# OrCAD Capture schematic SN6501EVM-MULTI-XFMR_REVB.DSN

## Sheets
1 P01 3p3V No LDO: size A; title: SN6501EVM-Multi-Xfmr; note: 6566239
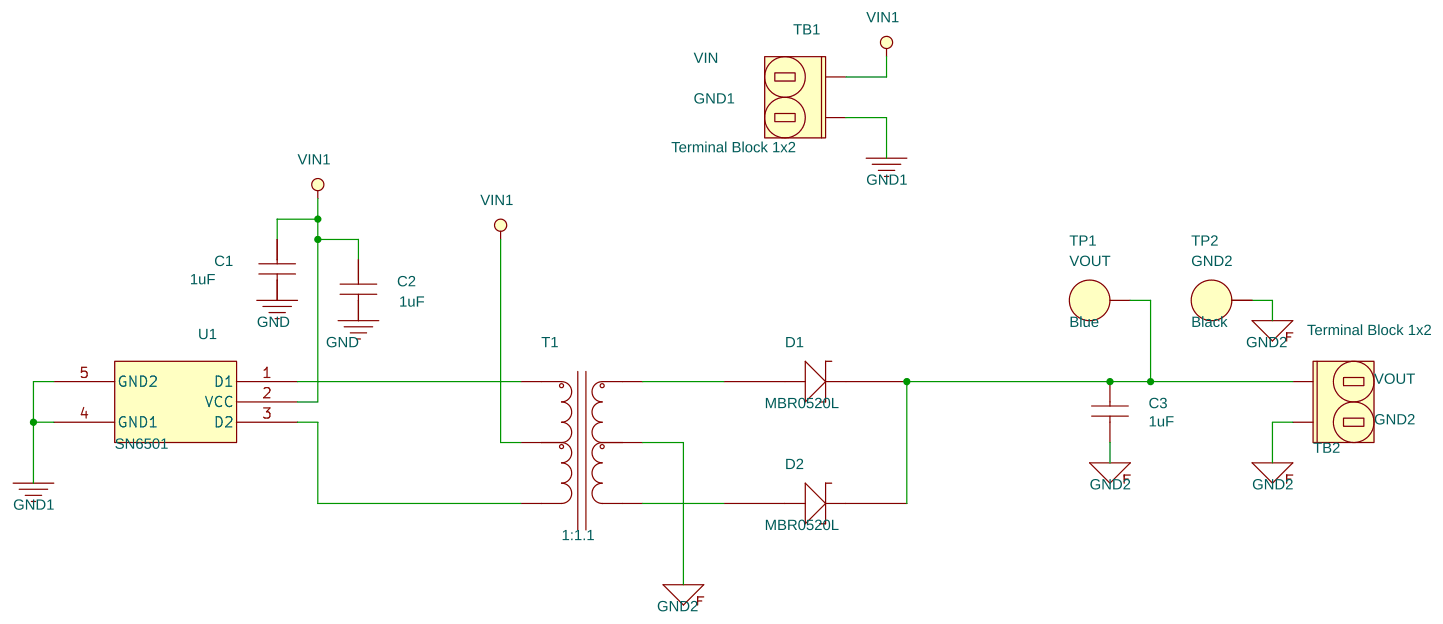
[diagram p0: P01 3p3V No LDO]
2 P02 5V No LDO: size A
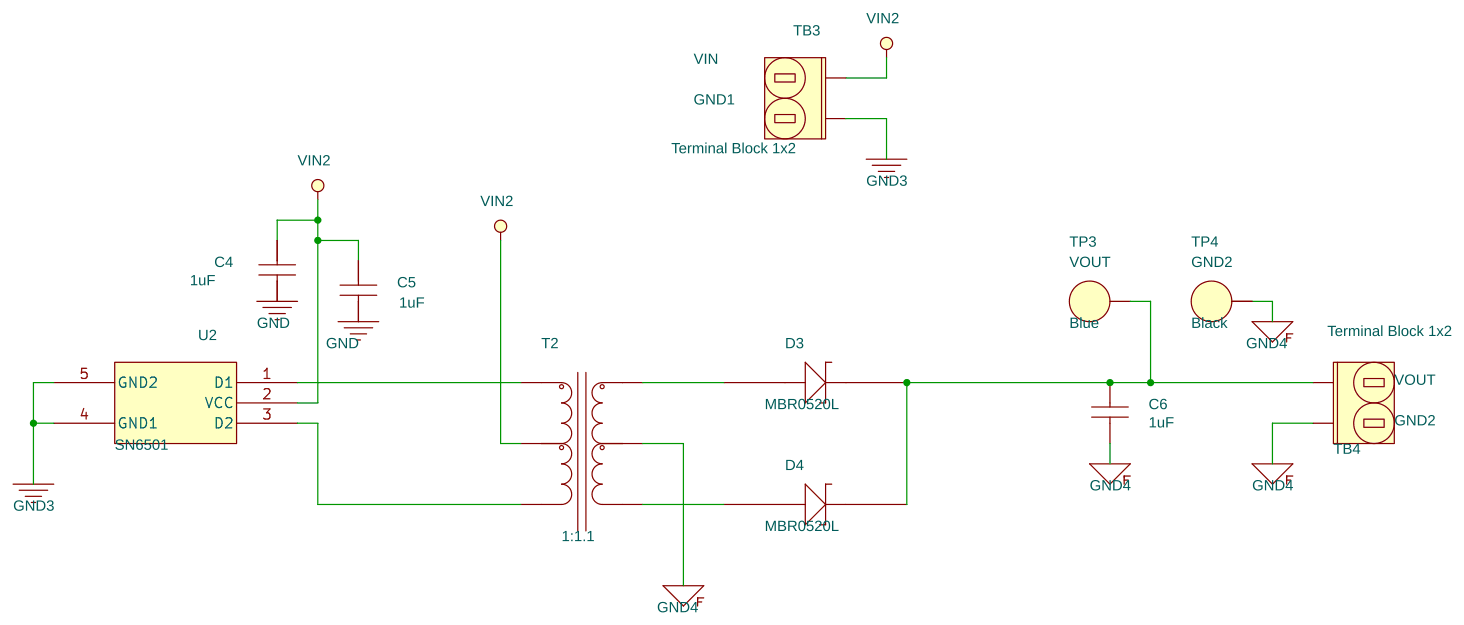
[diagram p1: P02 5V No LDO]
3 P03 3p3V to 5V No LDO: size A
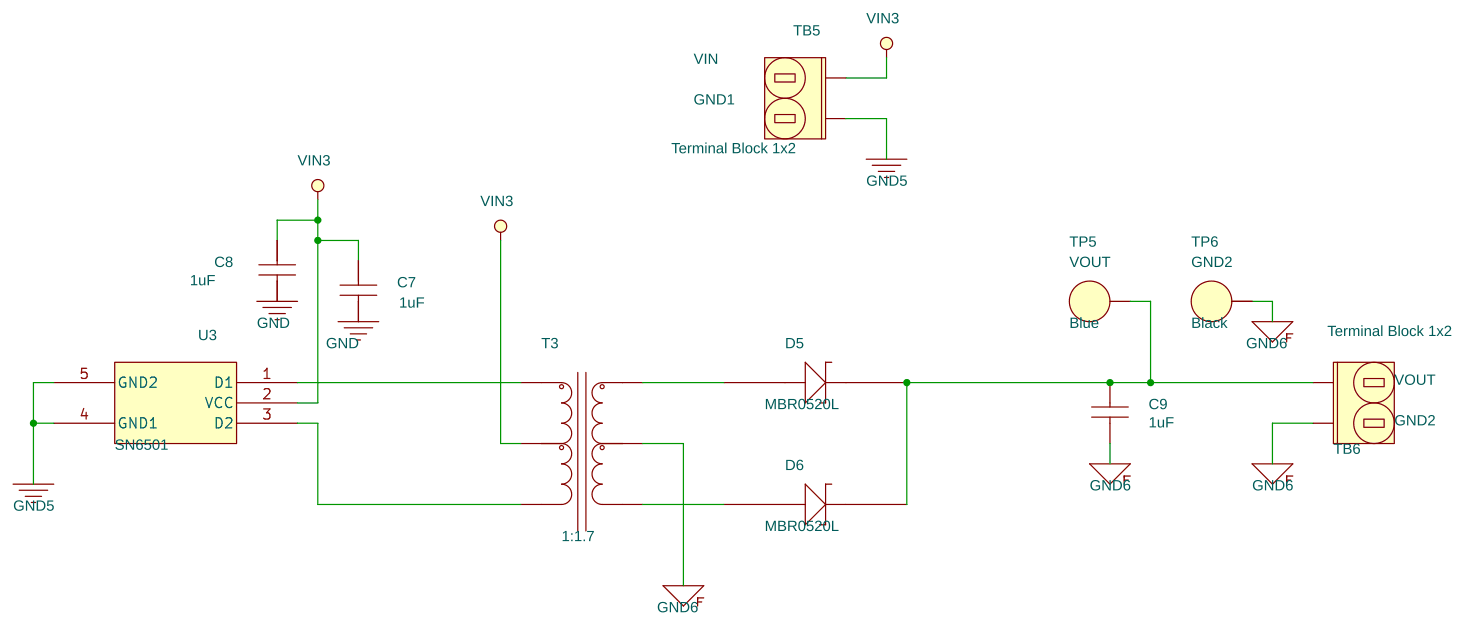
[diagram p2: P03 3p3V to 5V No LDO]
4 P04 3p3V to 5V LDO: size A
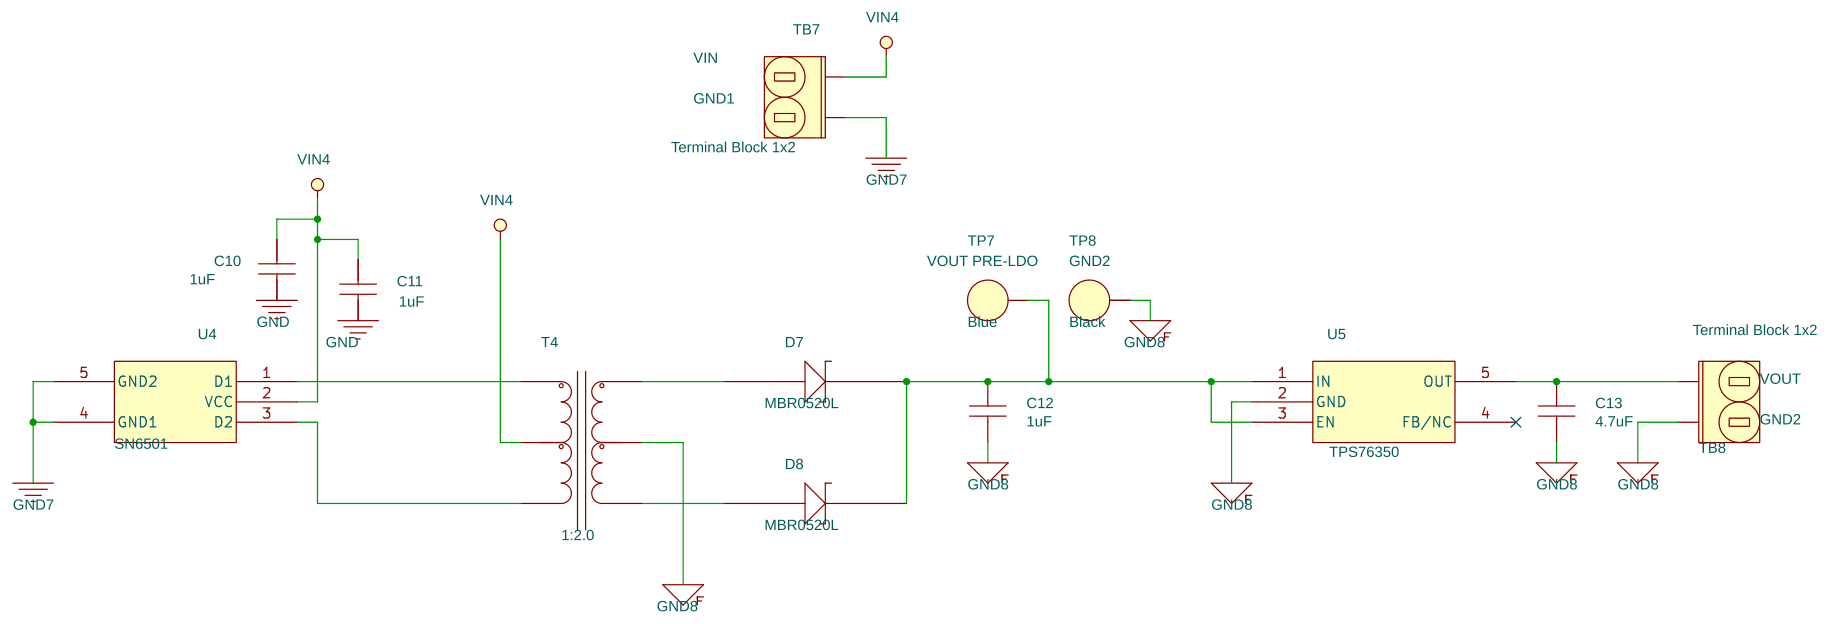
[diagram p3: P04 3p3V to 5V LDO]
5 P05 3p3V or 5V to 3p3V 5V LDO: size A
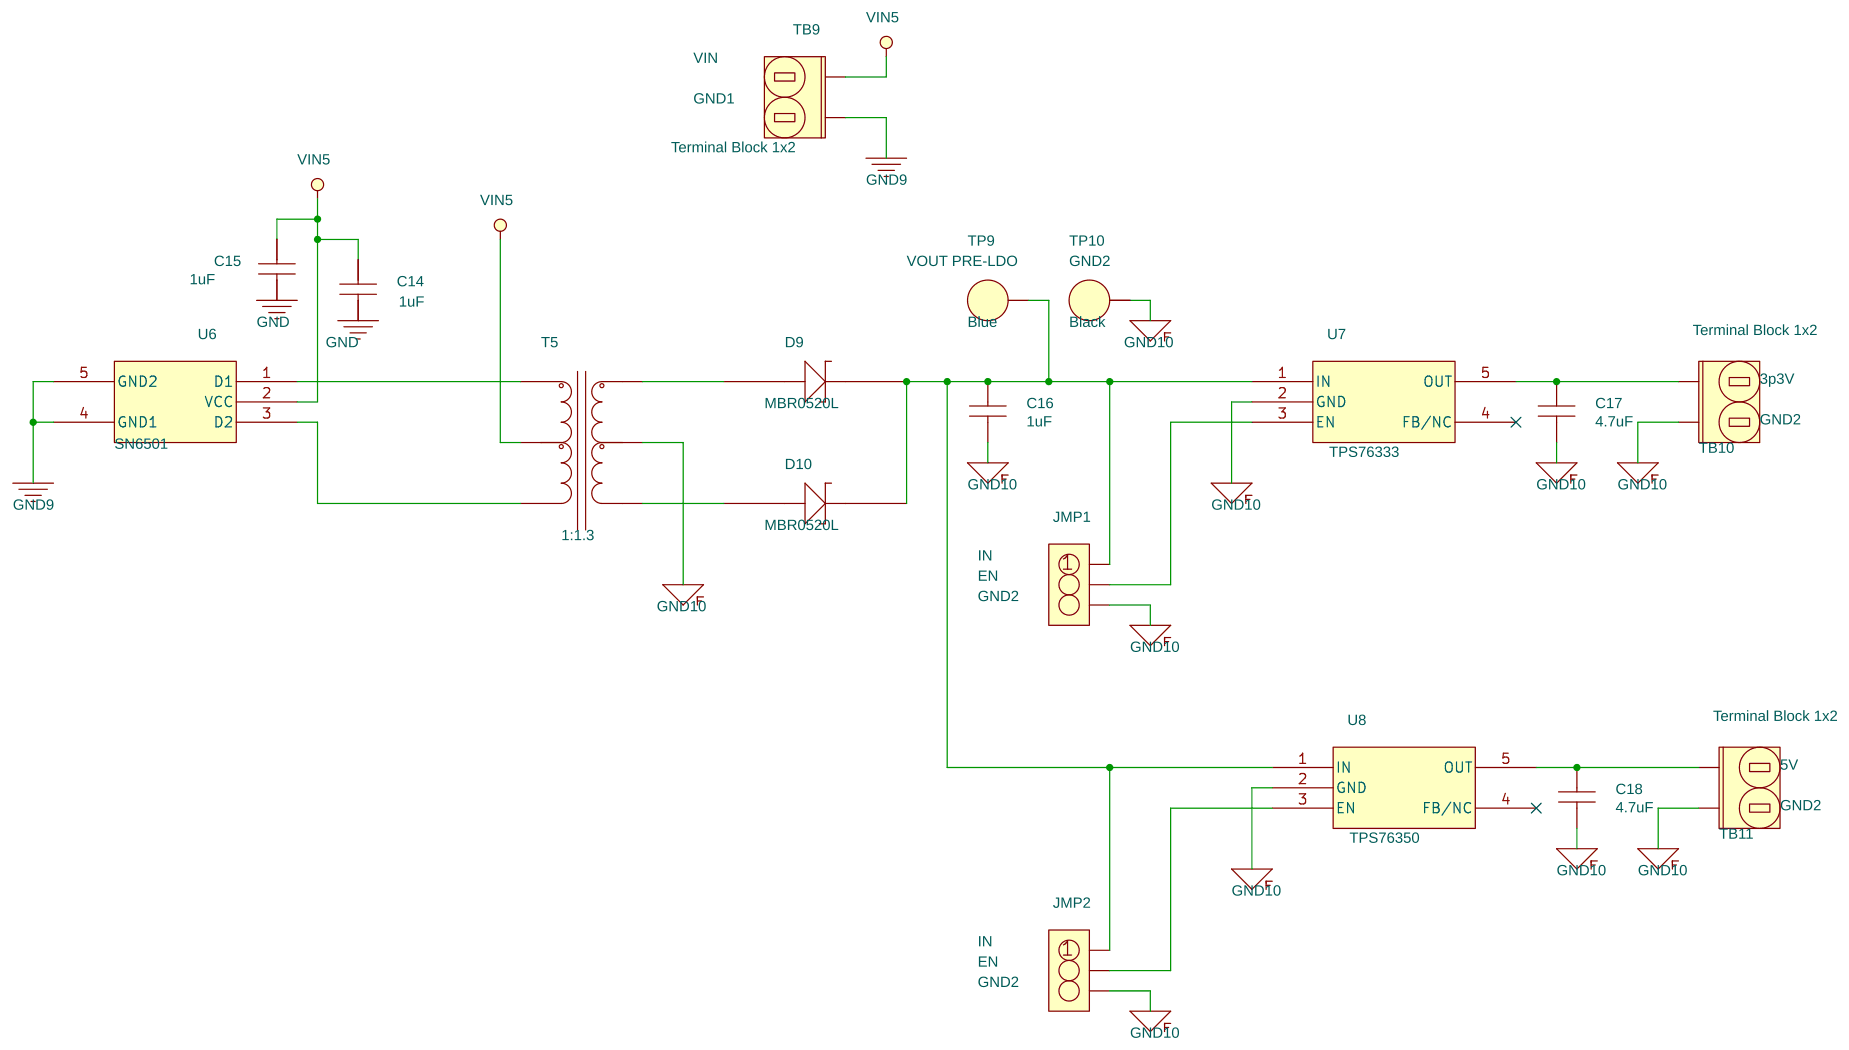
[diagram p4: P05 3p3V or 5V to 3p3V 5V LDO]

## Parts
sheet P01 3p3V No LDO
C1  1uF  [0402]
C2  1uF  [0603]
C3  1uF  [0603]
D1  MBR0520L  [SOD123]
D2  MBR0520L  [SOD123]
T1  1:1.1  [Wurth_76039xxxx]
TB1  Terminal Block 1x2  [TB_THRTSCR_1x2_100]
TB2  Terminal Block 1x2  [TB_THRTSCR_1x2_100]
TP1  Blue  [HDR_THVT_1X1_100]
TP2  Black  [HDR_THVT_1X1_100]
U1  SN6501  [SOT_5DBV]
sheet P02 5V No LDO
C4  1uF  [0402]
C5  1uF  [0603]
C6  1uF  [0603]
D3  MBR0520L  [SOD123]
D4  MBR0520L  [SOD123]
T2  1:1.1  [Wurth_76039xxxx]
TB3  Terminal Block 1x2  [TB_THRTSCR_1x2_100]
TB4  Terminal Block 1x2  [TB_THRTSCR_1x2_100]
TP3  Blue  [HDR_THVT_1X1_100]
TP4  Black  [HDR_THVT_1X1_100]
U2  SN6501  [SOT_5DBV]
sheet P03 3p3V to 5V No LDO
C7  1uF  [0603]
C8  1uF  [0402]
C9  1uF  [0603]
D5  MBR0520L  [SOD123]
D6  MBR0520L  [SOD123]
T3  1:1.7  [Wurth_76039xxxx]
TB5  Terminal Block 1x2  [TB_THRTSCR_1x2_100]
TB6  Terminal Block 1x2  [TB_THRTSCR_1x2_100]
TP5  Blue  [HDR_THVT_1X1_100]
TP6  Black  [HDR_THVT_1X1_100]
U3  SN6501  [SOT_5DBV]
sheet P04 3p3V to 5V LDO
C10  1uF  [0402]
C11  1uF  [0603]
C12  1uF  [0603]
C13  4.7uF  [0603]
D7  MBR0520L  [SOD123]
D8  MBR0520L  [SOD123]
T4  1:2.0  [Wurth_76039xxxx]
TB7  Terminal Block 1x2  [TB_THRTSCR_1x2_100]
TB8  Terminal Block 1x2  [TB_THRTSCR_1x2_100]
TP7  Blue  [HDR_THVT_1X1_100]
TP8  Black  [HDR_THVT_1X1_100]
U4  SN6501  [SOT_5DBV]
U5  TPS76350  [SOT_5DBV]
sheet P05 3p3V or 5V to 3p3V 5V LDO
C14  1uF  [0603]
C15  1uF  [0402]
C16  1uF  [0603]
C17  4.7uF  [0603]
C18  4.7uF  [0603]
D9  MBR0520L  [SOD123]
D10  MBR0520L  [SOD123]
JMP1  Header 1x3  [HDR_THVT_1X3_100]
JMP2  Header 1x3  [HDR_THVT_1X3_100]
T5  1:1.3  [Wurth_76039xxxx]
TB9  Terminal Block 1x2  [TB_THRTSCR_1x2_100]
TB10  Terminal Block 1x2  [TB_THRTSCR_1x2_100]
TB11  Terminal Block 1x2  [TB_THRTSCR_1x2_100]
TP9  Blue  [HDR_THVT_1X1_100]
TP10  Black  [HDR_THVT_1X1_100]
U6  SN6501  [SOT_5DBV]
U7  TPS76333  [SOT_5DBV]
U8  TPS76350  [SOT_5DBV]

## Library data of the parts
C1 C2 C4 C5 C7 C8 C10 C11 C14 C15 = cc0402
C3 C6 C9 C12 C13 C16-C18 = cc0805: Manufacturer: Murata; T_TEMPERATURE: X5R; VOLTAGE: 16V
D1-D10 = Zener_Diode: Manufacturer: Fairchild
T1 = T_Wurth_7603900xx: Manufacturer: Wurth; Manufacturer Part Number: 760390011
TB1 TB3 TB5 TB7 TB9 = Terminal_Block_1x2: SILKTEXT1: VIN; SILKTEXT2: GND1
TB2 TB4 TB6 TB8 = Terminal_Block_1x2: SILKTEXT1: GND2; SILKTEXT2: VOUT
TP1 TP3 TP5 = Test_Point: SILKTEXT1: VOUT
TP2 TP4 TP6 TP8 TP10 = Test_Point: SILKTEXT1: GND2
U1 U2 U4 U6 = SN6501_0
T2 = T_Wurth_7603900xx: Manufacturer: Wurth; Manufacturer Part Number: 760390012
T3 = T_Wurth_7603900xx: Manufacturer: Wurth; Manufacturer Part Number: 760390013
U3 = SN6501_0: Manufacturer: TI; Manufacturer Part Number: SN6501DBV
T4 = T_Wurth_7603900xx: Manufacturer: Wurth; Manufacturer Part Number: 760390015
TP7 TP9 = Test_Point: SILKTEXT1: VOUT PRE-LDO
U5 U8 = TPS763XX_0: Manufacturer: TI; Manufacturer Part Number: TPS76350DBV
JMP1 JMP2 = Header_1x3: SILKTEXT1: IN; SILKTEXT2: EN; SILKTEXT3: GND2
T5 = T_Wurth_7603900xx: Manufacturer: Wurth; Manufacturer Part Number: 760390014
TB10 = Terminal_Block_1x2: SILKTEXT1: GND2; SILKTEXT2: 3p3V
TB11 = Terminal_Block_1x2: SILKTEXT1: GND2; SILKTEXT2: 5V
U7 = TPS763XX_0: Manufacturer: TI; Manufacturer Part Number: TPS76333DBV

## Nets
GND1: C1.2 C2.2 TB1.2 U1.4(GND1) U1.5(GND2)
GND2: C3.2 T1.5 TB2.1 TP2.1
GND3: C4.2 C5.2 TB3.2 U2.4(GND1) U2.5(GND2)
GND4: C6.2 T2.5 TB4.1 TP4.1
GND5: C7.2 C8.2 TB5.2 U3.4(GND1) U3.5(GND2)
GND6: C9.2 T3.5 TB6.1 TP6.1
GND7: C10.2 C11.2 TB7.2 U4.4(GND1) U4.5(GND2)
GND8: C12.2 C13.2 T4.5 TB8.1 TP8.1 U5.2(GND)
GND9: C14.2 C15.2 TB9.2 U6.4(GND1) U6.5(GND2)
GND10: C16.2 C17.2 C18.2 JMP1.3 JMP2.3 T5.5 TB10.1 TB11.1 TP10.1 U7.2(GND) U8.2(GND)
VIN1: C1.1 C2.1 T1.2 TB1.1 U1.2(VCC)
VIN2: C4.1 C5.1 T2.2 TB3.1 U2.2(VCC)
VIN3: C7.1 C8.1 T3.2 TB5.1 U3.2(VCC)
VIN4: C10.1 C11.1 T4.2 TB7.1 U4.2(VCC)
VIN5: C14.1 C15.1 T5.2 TB9.1 U6.2(VCC)
N33604: T2.1 U2.3(D2)
N4691443: T2.3 U2.1(D1)
N4692106: C6.1 D3.2 D4.2 TB4.2 TP3.1
N4692138: D4.1 T2.4
N4692144: D3.1 T2.6
N4712324: T3.1 U3.3(D2)
N4712344: T3.3 U3.1(D1)
N4712346: C9.1 D5.2 D6.2 TB6.2 TP5.1
N4712350: D6.1 T3.4
N4712352: D5.1 T3.6
N4713737: T1.1 U1.3(D2)
N4713757: T1.3 U1.1(D1)
N4713759: C3.1 D1.2 D2.2 TB2.2 TP1.1
N4713763: D2.1 T1.4
N4713765: D1.1 T1.6
N4714851: T4.1 U4.3(D2)
N4714871: T4.3 U4.1(D1)
N4714873: C12.1 D7.2 D8.2 TP7.1 U5.1(IN) U5.3(EN)
N4714877: D8.1 T4.4
N4714879: D7.1 T4.6
N4714919: C13.1 TB8.2 U5.5(OUT)
N4716804: T5.1 U6.3(D2)
N4716844: T5.3 U6.1(D1)
N4716848: C16.1 D9.2 D10.2 JMP1.1 JMP2.1 TP9.1 U7.1(IN) U8.1(IN)
N4716856: D10.1 T5.4
N4716860: D9.1 T5.6
N4716940: C17.1 TB10.2 U7.5(OUT)
N4717316: JMP1.2 U7.3(EN)
N4717779: C18.1 TB11.2 U8.5(OUT)
N4717916: JMP2.2 U8.3(EN)

Not connected (* = marked no-connect by the designer): U5 4(FB/NC)*; U7 4(FB/NC)*; U8 4(FB/NC)*
